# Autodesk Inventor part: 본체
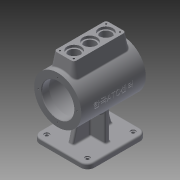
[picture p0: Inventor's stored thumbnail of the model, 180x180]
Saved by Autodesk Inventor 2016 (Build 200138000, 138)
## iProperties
Created: 2015-11
Part Number: 본체
Material: 일반
Document SubType Name: Modeling
Designer: mduedu
Density: 1 g/cm^3
Appearance: 기본값
Mass: 549.607 g
Surface Area: 1334.28 cm^2
Volume: 549.607 cm^3
Author: mduedu
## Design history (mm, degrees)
sketch "스케치2"
  geometry: C1 r 47.5 at (0, 0); 1 further point
  constraints: 1 centre point, 1 coincident
  dimensions: "d147" = 95 diameter of C1
extrude "돌출1" new body sketch "스케치2" stored distance "d12" = 130; taper "d13" = 0 deg
feature "쉘1" dims "d31" = 15, "d32" = 6, "d33" = 15
sketch "스케치5"
  geometry: C1 r 32.5 at (0, 0); 1 further point
  constraints: 1 centre point, 1 coincident
  dimensions: "d34" = 65 diameter of C1
extrude "돌출3" cut sketch "스케치5" stored distance "d36" = 3; taper "d37" = 0 deg
node "작업 평면1"
sketch "스케치6"
  geometry: L1 (-60, -55)-(60, -55); L2 (60, -55)-(60, 55); L3 (60, 55)-(-60, 55); L4 (-60, 55)-(-60, -55); L5 (-60, -55)-(60, 55); L6 (60, -55)-(-60, 55); 1 further point
  constraints: 12 end point, 2 midpoint, 2 parallel, 1 horizontal, 1 perpendicular
  dimensions: "d41" = 110 distance of L3.end L1.start; "d43" = 120 distance of L2.end L3.end
extrude "돌출4" join sketch "스케치6" distance "d44" = 10; taper "d45" = 0 deg
sketch "스케치19"
  geometry: L1 (-5, 35)-(5, 35); L2 (5, 35)-(5, -35); L3 (5, -35)-(-5, -35); L4 (-5, -35)-(-5, 35); L5 (-60, 55)-(-60, -55) reference; L6 (5, -35)-(-5, 35); L7 (5, 35)-(-5, -35); 3 further points
  constraints: 12 end point, 2 midpoint, 2 parallel, 1 coincident, 1 horizontal, 1 horizontal alignment, 1 perpendicular
  dimensions: "d151" = 10 distance of L1.start L1.end; "d152" = 70 distance of L3.end L1.start
extrude "돌출9" join sketch "스케치19" stored distance "d153" = 10; taper "d154" = 0 deg
sketch "스케치20"
  geometry: L1 (65, 32.5)-(50, 32.5) reference; L2 (50, 32.5)-(50, 41.5) reference; L3 (50, 41.5)-(-50, 41.5) reference; L4 (-50, 41.5)-(-50, 32.5) reference; L5 (-50, 32.5)-(-65, 32.5) reference; L6 (-65, 32.5)-(-65, 47.5) reference; L7 (-65, 47.5)-(65, 47.5) reference; L8 (65, 47.5)-(65, 32.5) reference; L9 (50, -32.5)-(65, -32.5) reference; L10 (65, -32.5)-(65, -47.5) reference; L11 (65, -47.5)-(5, -47.5) reference; L12 (5, -47.5)-(5, -90) reference; L13 (5, -90)-(60, -90) reference; L14 (60, -90)-(60, -100) reference; L15 (60, -100)-(-60, -100) reference; L16 (-60, -100)-(-60, -90) reference; L17 (-60, -90)-(-5, -90) reference; L18 (-5, -90)-(-5, -47.5) reference; L19 (-5, -47.5)-(-65, -47.5) reference; L20 (-65, -47.5)-(-65, -32.5) reference; L21 (-65, -32.5)-(-50, -32.5) reference; L22 (-50, -32.5)-(-50, -41.5) reference; L23 (-50, -41.5)-(50, -41.5) reference; L24 (50, -41.5)-(50, -32.5) reference; L25 (-40, -90)-(-28.612, -47.5); 1 further point
  constraints: 2 end point, 2 point on line
  dimensions: "d155" = 20 distance from line of L25.start L16; "d156" = 105 deg angle of L25 L17
feature "리브2" sketch "스케치20" dims "d157" = 1, "d158" = 10, "d159" = 0, "d160" = 0, "d161" = 1, "d162" = 1
fillet "모깎기21" dims "d163" = 3
fillet "모깎기22" dims "d164" = 3
fillet "모깎기23" dims "d165" = 3
sketch "스케치21" dims "d166" = 78
  geometry: 3 further points
  constraints: 2 horizontal alignment, 1 coincident, 2 other
hole "구멍6" sketch "스케치21" at (39, 0) diameter "d168" = 3.242; stored, may be unused: countersink angle "d172" = 90 deg, drill point angle "d174" = 118 deg; dims "d169" = 9, "d170" = 4, "d171" = 2, "d173" = 11
node "작업 평면2"
sketch "스케치13"
  geometry: L1 (-52.5, -20)-(52.5, -20); L2 (52.5, -20)-(52.5, 20); L3 (52.5, 20)-(-52.5, 20); L4 (-52.5, 20)-(-52.5, -20); L5 (-52.5, -20)-(52.5, 20); L6 (52.5, -20)-(-52.5, 20); 1 further point
  constraints: 12 end point, 2 midpoint, 2 parallel, 1 horizontal, 1 perpendicular
  dimensions: "d93" = 105 distance of L2.end L3.end; "d95" = 40 distance of L1.end L2.end
extrude "돌출8" join sketch "스케치13" stored distance "d96" = 80; taper "d97" = 0 deg
fillet "모깎기15" dims "d98" = 5
feature "면 기울기1" dims angle "d178" = 10 deg
fillet "모깎기24" dims "d179" = 3
sketch "스케치14"
  geometry: L1 (-52.5, 15)-(-52.5, -15) reference; L2 (52.5, -15)-(52.5, 15) reference; L3 (-52.5, 0)-(52.5, 0); 4 further points
  constraints: 2 end point, 2 midpoint, 2 point on line, 1 coincident
  dimensions: "d100" = 32 distance of point (-32, 0) point (0, 0); "d102" = 32 distance of point (32, 0) point (0, 0) (derived)
hole "구멍3" sketch "스케치14" at (-32, 0), (0, 0), (32, 0) diameter "d103" = 22; stored, may be unused: countersink angle "d107" = 90 deg, drill point angle "d109" = 118 deg; dims "d104" = 8, "d105" = 28, "d106" = 5, "d108" = 10
sketch "스케치15"
  geometry: L1 (46.5, -14)-(-46.5, -14); L2 (-46.5, -14)-(-46.5, 14); L3 (-46.5, 14)-(46.5, 14); L4 (46.5, 14)-(46.5, -14); L5 (46.5, -14)-(-46.5, 14); L6 (-46.5, -14)-(46.5, 14); L7 (47.5, 20)-(-47.5, 20) reference; L8 (-52.5, 15)-(-52.5, -15) reference; 5 further points
  constraints: 12 end point, 4 coincident, 2 midpoint, 2 parallel, 1 horizontal, 1 perpendicular
  dimensions: "d110" = 6 distance between parallel lines of L3 L7; "d111" = 6 distance between parallel lines of L2 L8
hole "구멍4" sketch "스케치15" at (-46.5, 14), (46.5, 14), (46.5, -14), (-46.5, -14) diameter "d112" = 3.242; stored, may be unused: countersink angle "d116" = 90 deg, drill point angle "d118" = 118 deg; dims "d113" = 10, "d114" = 28, "d115" = 5, "d117" = 13
node "작업 평면3"
sketch "스케치22"
  geometry: 2 further points
  constraints: 1 coincident, 1 other
feature "엠보싱3" sketch "스케치22" dims "d31" = 15, "d181" = 0.5, "d182" = 0
chamfer "모따기2" distance "d183" = 1; stored, may be unused: second distance "d184" = 2, angle "d185" = 45 deg
fillet "모깎기25" dims "d186" = 14
sketch "스케치23"
  geometry: L1 (46, 55)-(-46, 55) reference; L2 (60, -41)-(60, 41) reference; L3 (-46, -55)-(46, -55) reference; L4 (-60, 41)-(-60, -41) reference; A1 r 14 centre (-46, 41) between (-46, 55) and (-60, 41) reference; A2 r 14 centre (46, 41) between (60, 41) and (46, 55) reference; A3 r 14 centre (46, -41) between (46, -55) and (60, -41) reference; A4 r 14 centre (-46, -41) between (-60, -41) and (-46, -55) reference; 1 further point
hole "구멍7" sketch "스케치23" at (-46, 41), (-46, -41), (46, -41), (46, 41) diameter "d187" = 6; stored, may be unused: countersink angle "d191" = 90 deg, drill point angle "d193" = 118 deg; dims "d188" = 9, "d189" = 10, "d190" = 2, "d192" = 11
fillet "모깎기26" dims "d194" = 3
node "솔리드1"
mirror "대칭6"
pattern_circular "원형 패턴2" dims angle "d176" = 360 deg
mirror "대칭5"
node "투영된 루프2"
node "절단 모서리 투영1"
